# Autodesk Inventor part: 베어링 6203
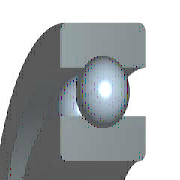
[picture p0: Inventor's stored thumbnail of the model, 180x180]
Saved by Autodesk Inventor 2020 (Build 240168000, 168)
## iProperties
IsCustomPart: 0
Created: 2009-02
Part Number: 베어링 6203
Material: 강철, 연강
Description: 깊은 그루브 볼 베어링
Document SubType Name: Modeling
Standard: KS B 2023
Standards Organization: KS
Language: ko-KR
Size Designation: 6203 - 17 x 40 x 12
Categories: <MemberInstance><Categories><Category DisplayName="샤프트 부품" InternalName="7f7aeb1f-a693-4053-b835-cee3144e0d98" Mnemonic="SHFT"><Category DisplayName="베어링" Inter
Density: 1 g/cm^3
Appearance: 밝은 황색
Author: pww
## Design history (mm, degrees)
sketch "스케치" dims "d0" = 5.98 (= -0.26 x WD + 0.26 x BD)
  geometry: L1 (3.01, 14.25)-(8.99, 14.25); L2 (6, 14.25)-(6, 11.26); L3 (6, 14.25)-(6, 17.24); L4 (3.778, 12.249)-(0, 12.249); L5 (0, 8.5)-(12, 8.5); L6 (3.778, 16.251)-(0, 16.251); L7 (0, 20)-(12, 20); L8 (12, 8.5)-(12, 12.249); L9 (8.222, 12.249)-(12, 12.249); L10 (8.222, 16.251)-(12, 16.251); L11 (12, 20)-(12, 16.251); L12 (-1.4, 0)-(8.4, 0) reference; L13 (0, -0.3)-(0, 5.3) reference
  constraints: 22 end point, 4 point on line, 2 collinear, 2 perpendicular, 2 symmetric about line, 1 midpoint, 1 parallel, 14 other
  dimensions: "d9" = 17 diameter of L5 L12 (= WD); "d11" = 40 diameter of L7 L12 (= BD); "d12" = 12 distance between parallel lines of L8 L13 (= KB); "d13" = 24.498 diameter of L9 L12 (= 0.326 x BD + 0.674 x WD)
revolve "본체" stored, may be unused: angle "d6" = 90 deg
revolve "볼" stored, may be unused: angle "d7" = 90 deg
pattern_circular "IDS_ARRAYBALL[SIMPL:T]" dims angle "d3" = 360 deg
body "Solid1"
fillet "모깎기1" dims "d1" = 0.6 (= KRS)
other parameters: "WD" = 17 [user parameter; used in 5 equation terms], "BD" = 40 [user parameter; used in 5 equation terms], "KB" = 12 [user parameter; used in 1 equation term], "KRS" = 0.6 [user parameter; used in 1 equation term], "d4" = 0, "d5" = 0, "d8" = 0, "d14" = 0, "d15" = 0, "BBA" = 0 [user parameter], "BC0" = 4750000 [user parameter], "BC" = 9560000 [user parameter], "WR" = 8.5 (= 0.5 x WD) [user parameter]
